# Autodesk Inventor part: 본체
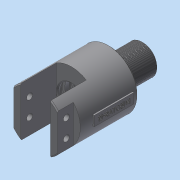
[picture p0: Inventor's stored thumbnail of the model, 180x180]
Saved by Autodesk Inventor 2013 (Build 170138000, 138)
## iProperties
Created: 2019-02
Part Number: 본체
Material: Generic
Document SubType Name: Modeling
Designer: Administrator
Density: 1 g/cm^3
Author: Administrator
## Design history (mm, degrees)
sketch "스케치1"
  geometry: C1 r 29 at (0, 0); 1 further point
  constraints: 1 centre point, 1 coincident
  dimensions: "d0" = 58 diameter of C1
extrude "돌출1" new body sketch "스케치1" distance "d3" = 74; taper "d4" = 0 deg
sketch "스케치2"
  geometry: L1 (-15, 24.819)-(-15, -24.819); L2 (15, 24.819)-(15, -24.819); A1 r 29 centre (0, 0) between (-15, 24.819) and (-15, -24.819) reference; A2 r 29 centre (0, 0) between (-15, 24.819) and (-15, -24.819) reference
  constraints: 8 point on circle, 4 end point, 2 vertical, 1 parallel
  dimensions: "d5" = 30 distance between parallel lines of L2 L1
extrude "돌출2" cut sketch "스케치2" distance "d6" = 36; taper "d7" = 0 deg
sketch "스케치3"
  geometry: L1 (22, 18.894)-(22, -18.894); A1 r 29 centre (0, 0) between (15, -24.819) and (15, 24.819) reference
  constraints: 2 end point, 2 point on circle, 1 vertical
  dimensions: "d8" = 22 distance from line of L1 A1.centre
extrude "돌출3" cut sketch "스케치3" distance "d9" = 16; taper "d10" = 0 deg
sketch "스케치4"
  geometry: C1 r 29 at (0, 0) reference; C2 r 13 at (0, 0)
  constraints: 1 centre point, 1 coincident
  dimensions: "d11" = 26 diameter of C2
extrude "돌출4" join sketch "스케치4" distance "d14" = 5; taper "d15" = 0 deg
sketch "스케치5"
  geometry: C1 r 13 at (0, 0) reference; C2 r 15 at (0, 0)
  constraints: 1 centre point, 1 coincident
  dimensions: "d16" = 30 diameter of C2
extrude "돌출5" join sketch "스케치5" distance "d18" = 29; taper "d19" = 0 deg
sketch "스케치6"
  geometry: 1 further point
sketch "스케치7"
  geometry: L1 (18.894, 58)-(18.894, 74) reference; L2 (24.819, 74)-(18.894, 74) reference; L3 (24.819, 74)-(24.819, 38) reference; L4 (24.819, 38)-(24.819, 38) reference; L5 (24.819, 38)-(24.819, 74) reference; L6 (18.894, 74)-(24.819, 74) reference; L7 (18.894, 74)-(18.894, 58) reference; L8 (18.894, 58)-(-18.894, 58) reference; L9 (-18.894, 58)-(-18.894, 74) reference; L10 (-24.819, 74)-(-18.894, 74) reference; L11 (-24.819, 74)-(-24.819, 38) reference; L12 (-24.819, 38)-(-24.819, 38) reference; L13 (-24.819, 38)-(-24.819, 74) reference; L14 (-18.894, 74)-(-24.819, 74) reference; L15 (-18.894, 74)-(-18.894, 58) reference; L16 (-18.894, 58)-(18.894, 58) reference; L17 (-29, 0)-(29, 0) reference; L18 (-15, -34)-(15, -34) reference; L19 (15, -5)-(-15, -5) reference; L20 (-13, -5)-(13, -5) reference; L21 (13, 0)-(-13, 0) reference; L22 (0, 38)-(0, -34); L23 (-24.819, 38)-(24.819, 38) reference; L24 (14, 38)-(14, 35.35); L25 (14, 35.35)-(17, 35.35); L26 (17, 35.35)-(17, 30.65); L27 (17, 30.65)-(14, 30.65); L28 (14, 26.35)-(17, 26.35); L29 (17, 26.35)-(17, 21.65); L30 (17, 21.65)-(14, 21.65); L31 (14, 21.65)-(14, 18); L32 (14, 18)-(16, 18); L33 (16, 18)-(16, 11); L34 (16, 11)-(4, 11); L35 (4, 11)-(4, -12); L36 (4, -12)-(0, -12); L37 (14, 30.65)-(14, 26.35); 5 further points
  constraints: 30 end point, 9 parallel, 6 midpoint, 4 collinear, 4 point on line, 3 perpendicular, 1 vertical alignment
  dimensions: "d20" = 20 distance from line of L23 L32.end; "d21" = 28 diameter of L24 L22; "d22" = 34 diameter of L26 L22; "d23" = 4.7 distance of L25.end L26.end; "d24" = 9 distance of L29.end L26.end; "d25" = 7.35 distance from line of L26.end L23; "d26" = 7 distance of L32.end L33.end; "d27" = 32 diameter of L33 L22; "d28" = 8 diameter of L35 L22; "d30" = 22 distance between parallel lines of L18 L36
revolve "회전1" sketch "스케치7" stored, may be unused: angle "d31" = 90 deg
sketch "스케치8"
  geometry: C1 r 15 at (0, 0) reference; 1 further point
  constraints: 1 coincident
sketch "스케치9"
  geometry: L1 (0, 37.789)-(0, 0) reference; L2 (-16, 37.789)-(0, 37.789) reference; L3 (0, 43.714)-(0, 37.789) reference; L4 (0, 43.714)-(-36, 43.714) reference; L5 (-36, 43.714)-(-36, 43.714) reference; L6 (-36, 43.714)-(0, 43.714) reference; L7 (0, 37.789)-(0, 43.714) reference; L8 (0, 37.789)-(-16, 37.789) reference; L9 (-16, 37.789)-(-16, 0) reference; L10 (-16, 0)-(0, 0) reference; L11 (0, -5.925)-(0, 0) reference; L12 (0, -5.925)-(-36, -5.925) reference; L13 (-36, -5.925)-(-36, -5.925) reference; L14 (-36, -5.925)-(0, -5.925) reference; L15 (0, 0)-(0, -5.925) reference; L16 (0, 0)-(-16, 0) reference; L17 (-16, 0)-(-16, 37.789) reference; L18 (-74, 47.894)-(-74, -10.106) reference; L19 (-108, 33.894)-(-108, 3.894) reference; L20 (-79, 3.894)-(-79, 33.894) reference; L21 (-79, 31.894)-(-79, 5.894) reference; L22 (-74, 5.894)-(-74, 31.894) reference; L23 (-16, 37.789)-(-16, 0) reference; L24 (-63, 2.894)-(-63, 34.894) reference; L25 (-74, 47.894)-(-74, -10.106) reference; L26 (-74, 47.894)-(-36, 47.894) reference; L27 (-74, -10.106)-(-36, -10.106) reference; C1 r 3 at (-9, 27.894); C2 r 3 at (-9, 9.894); 1 further point
  constraints: 2 centre point, 1 equal radius, 1 vertical alignment
  dimensions: "d32" = 18 distance of C2.centre C1.centre; "d34" = 9 distance from line of C1.centre L1; "d35" = 20 vertical distance of C1.centre L26.end; "d36" = 6 diameter of C1
extrude "돌출6" cut sketch "스케치9" distance "d37" = 10; taper "d38" = 0 deg
node "작업 평면1"
sketch "스케치10"
  geometry: L1 (-5, 45)-(5, 45); L2 (5, 45)-(5, 5); L3 (5, 5)-(-5, 5); L4 (-5, 5)-(-5, 45); L5 (-5, 45)-(5, 5); L6 (5, 45)-(-5, 5); L7 (-29, 0)-(29, 0) reference; 3 further points
  constraints: 12 end point, 3 midpoint, 2 parallel, 1 horizontal, 1 perpendicular, 1 vertical alignment
  dimensions: "d40" = 40 distance of L1.end L2.end; "d42" = 10 distance of L1.start L1.end; "d43" = 5 distance between parallel lines of L3 L7
extrude "돌출7" join sketch "스케치10" stored distance "d44" = 1; taper "d45" = 0 deg
sketch "스케치11"
  geometry: L1 (45, 5)-(45, -5) reference; 2 further points
  constraints: 1 horizontal alignment, 1 other
  dimensions: "d46" = 20 distance from line of L1 point (25, 0)
feature "엠보싱1" sketch "스케치11" dims "d47" = 0.5, "d48" = 0
node "스케치12"
hole "구멍1" sketch "스케치8" diameter "d49" = 12.376; stored, may be unused: countersink angle "d53" = 90 deg, drill point angle "d55" = 118 deg; dims "d50" = 18, "d51" = 4, "d52" = 2, "d54" = 22
fillet "모깎기1" dims "d56" = 0.8
chamfer "모따기1" distance "d57" = 1; stored, may be unused: second distance "d58" = 2, angle "d59" = 45 deg
chamfer "모따기2" distance "d60" = 1; stored, may be unused: second distance "d61" = 2, angle "d62" = 45 deg
feature "스레드3" dims "d67" = 10, "d68" = 0
node "솔리드1"
mirror "대칭1"
mirror "대칭2"
node "투영된 루프1"
node "투영된 루프2"
node "투영된 루프3"
node "투영된 루프4"
node "투영된 루프5"
node "투영된 루프6"
node "투영된 루프7"
